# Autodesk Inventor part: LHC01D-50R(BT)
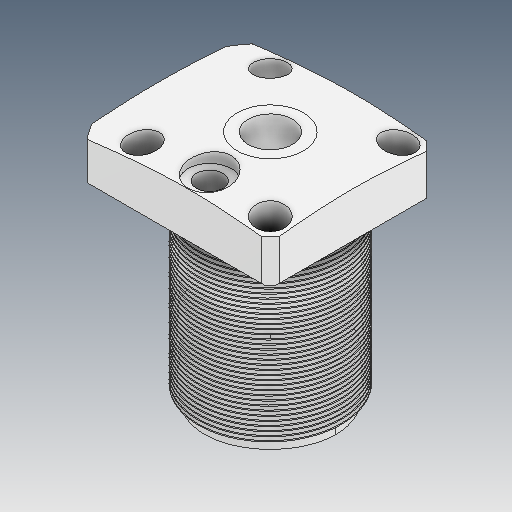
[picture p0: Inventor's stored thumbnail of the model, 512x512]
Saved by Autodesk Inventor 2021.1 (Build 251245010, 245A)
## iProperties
Created: 2021-06
Part Number: LHC01D-50R(BT)
Material: Ogólny
Document SubType Name: Modeling
Designer: user
Density: 1 g/cm^3
Appearance: Domyślna
Author: user
Revision Number: ÈÎºÎ
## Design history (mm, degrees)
feature "NONE"
node "Bryła1"
